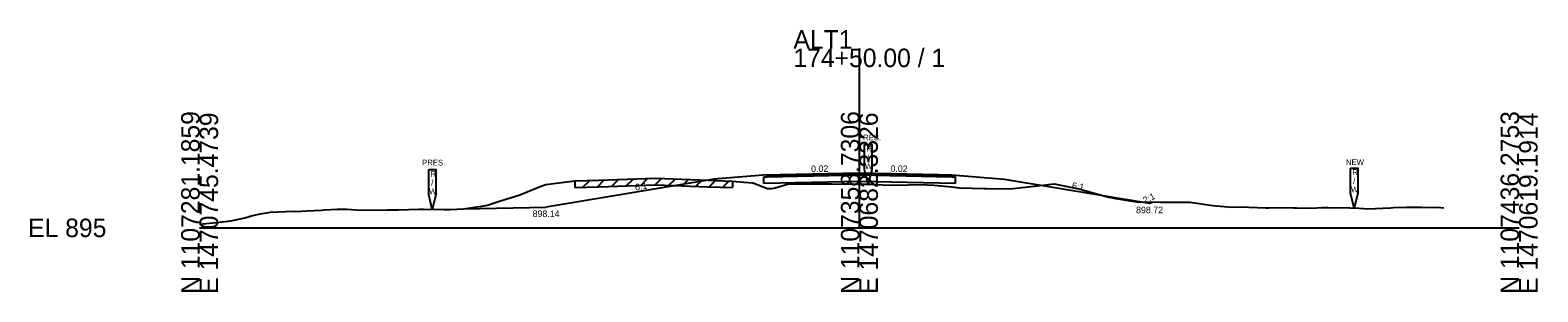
# Model space of a CAD drawing. Extents: x -26 to 2203, y -10 to 19568.
# Drawn here: x 974.3 to 1202.8, y 16490.3 to 16530 of the extents above; entities that cross this region are included whole.
import ezdxf

# ---------------------------------------------------------------- set-up
doc = ezdxf.new("R2010")
doc.units = 0
for name, color, linetype in [('RD_GPK_XS_Cell', 7, 'Continuous'), ('RD_XS_Base', 7, 'Continuous'), ('RD_XS_ExGround', 7, 'Continuous'), ('RD_XS_ExPaveRet', 7, 'Continuous'), ('RD_XS_ExRW', 7, 'Continuous'), ('RD_XS_Greenside', 7, 'Continuous'), ('RD_XS_NewRW', 7, 'Continuous'), ('RD_XS_Pave', 7, 'Continuous'), ('RD_XS_TieSlope', 7, 'Continuous'), ('RD_XS_TX_Ditch', 7, 'Continuous'), ('RD_XS_TX_Slope', 7, 'Continuous')]:
    doc.layers.add(name, color=color, linetype=linetype)

msp = doc.modelspace()

# ---------------------------------------------------------------- linework, layer by layer
at = {"layer": 'RD_GPK_XS_Cell'}
for p, q in [((1100, 16500), (1100, 16527.16)), ((1000, 16500), (1100, 16500)), ((1100, 16500), (1200, 16500))]:
    msp.add_line(p, q, dxfattribs=at)
at = {"layer": 'RD_XS_Base'}
for points in [[(1085.5, 16507.73), (1086, 16507.74), (1100, 16508.02), (1114, 16507.74), (1114.5, 16507.73)], [(1085.5, 16506.73), (1085.5, 16507.73)], [(1114.5, 16506.73), (1100, 16507.02), (1085.5, 16506.73)], [(1114.5, 16507.73), (1114.5, 16506.73)]]:
    msp.add_lwpolyline(points, dxfattribs=at)
at = {"layer": 'RD_XS_ExGround'}
msp.add_lwpolyline([(1000, 16500.56), (1002.98, 16500.88), (1004.71, 16501.05), (1006.85, 16501.54), (1008.02, 16501.87), (1009.46, 16502.16), (1010.16, 16502.29), (1010.72, 16502.36), (1014.21, 16502.51), (1014.59, 16502.5), (1016.25, 16502.59), (1018.46, 16502.68), (1018.96, 16502.75), (1020.82, 16502.83), (1022.33, 16502.83), (1023.71, 16502.75), (1026.2, 16502.7), (1028.47, 16502.74), (1030.07, 16502.75), (1033.22, 16502.81), (1033.93, 16502.83), (1037.08, 16502.77), (1037.97, 16502.77), (1040.01, 16502.89), (1042.78, 16503.3), (1043.63, 16503.43), (1045.45, 16504.04), (1048.54, 16505.03), (1051.61, 16506.26), (1052.46, 16506.56), (1054.85, 16506.89), (1056.87, 16507.12), (1060.44, 16507.24), (1069.16, 16507.51), (1077.08, 16507.21), (1080.78, 16507.1), (1082.51, 16506.92), (1083.83, 16506.8), (1086.05, 16505.94), (1086.79, 16505.94), (1087.21, 16506.06), (1089.28, 16506.67), (1091.72, 16506.69), (1093.32, 16506.67), (1094.98, 16506.67), (1095.83, 16506.67), (1100, 16506.64), (1101.85, 16506.61), (1103.57, 16506.51), (1104.49, 16506.48), (1107.44, 16506.53), (1109.24, 16506.58), (1111.31, 16506.46), (1113.99, 16506.2), (1115.18, 16506.09), (1118.92, 16505.96), (1119.3, 16505.95), (1122.88, 16505.9), (1126.94, 16506.37), (1129.51, 16506.66), (1133.5, 16505.87), (1134.52, 16505.57), (1137.74, 16504.64), (1138.1, 16504.58), (1138.88, 16504.45), (1141.99, 16503.96), (1142.75, 16503.94), (1145.63, 16503.87), (1146.69, 16503.88), (1147, 16503.89), (1150.11, 16503.9), (1153.58, 16503.38), (1156.42, 16503.14), (1157.78, 16503.21), (1161.6, 16503.06), (1162.05, 16503.06), (1165.47, 16503.08), (1165.82, 16503.05), (1166.25, 16503.03), (1167.95, 16502.97), (1169.34, 16503.05), (1170.09, 16503.09), (1171, 16503.07), (1172.22, 16503.06), (1173.21, 16503.09), (1174.35, 16503.06), (1175.75, 16502.96), (1177.08, 16502.88), (1180.51, 16503.05), (1180.95, 16503.07), (1182.88, 16503.12), (1184.81, 16503.13), (1185.26, 16503.13), (1187.15, 16503.11), (1187.69, 16503.16), (1188.59, 16503.04)], dxfattribs=at)
at = {"layer": 'RD_XS_ExPaveRet'}
for p, q in [((1056.87, 16507.06), (1056.93, 16507.13)), ((1056.87, 16507.12), (1056.87, 16506.12)), ((1058.09, 16506.16), (1059.12, 16507.2)), ((1060.28, 16506.23), (1061.32, 16507.27)), ((1062.47, 16506.3), (1063.51, 16507.33)), ((1064.66, 16506.37), (1065.69, 16507.4)), ((1066.85, 16506.44), (1067.88, 16507.47)), ((1069.04, 16506.51), (1070.01, 16507.48)), ((1071.09, 16506.44), (1072.06, 16507.4)), ((1073.14, 16506.36), (1074.1, 16507.32)), ((1075.18, 16506.28), (1076.15, 16507.25)), ((1077.23, 16506.21), (1078.2, 16507.18)), ((1079.29, 16506.15), (1080.26, 16507.12)), ((1080.78, 16507.1), (1080.78, 16506.1))]:
    msp.add_line(p, q, dxfattribs=at)
msp.add_lwpolyline([(1056.87, 16506.12), (1060.47, 16506.24), (1069.15, 16506.51), (1077.05, 16506.21), (1080.78, 16506.1)], dxfattribs=at)
at = {"layer": 'RD_XS_ExRW'}
for points in [[(1100.78, 16512.63), (1101.88, 16512.63), (1101.88, 16508.8), (1101.33, 16506.61), (1100.78, 16508.8)], [(1034.72, 16508.82), (1035.81, 16508.82), (1035.81, 16504.99), (1035.26, 16502.8), (1034.72, 16504.99)]]:
    msp.add_lwpolyline(points, close=True, dxfattribs=at)
at = {"layer": 'RD_XS_Greenside'}
msp.add_line((1040.01, 16502.89), (1052.52, 16503.14), dxfattribs=at)
for points in [[(1078, 16507.39), (1052.52, 16503.14)], [(1086, 16508.05), (1078, 16507.39)], [(1114, 16508.05), (1122, 16507.39)], [(1122, 16507.39), (1144, 16503.72)]]:
    msp.add_lwpolyline(points, dxfattribs=at)
at = {"layer": 'RD_XS_NewRW'}
msp.add_lwpolyline([(1174.45, 16509.03), (1175.55, 16509.03), (1175.55, 16505.2), (1175, 16503.01), (1174.45, 16505.2)], close=True, dxfattribs=at)
at = {"layer": 'RD_XS_Pave'}
for points in [[(1086, 16508.05), (1088, 16508.09), (1100, 16508.33), (1112, 16508.09), (1114, 16508.05)], [(1086, 16507.89), (1100, 16508.17), (1114, 16507.89)], [(1114, 16507.89), (1100, 16508.17), (1086, 16507.89)], [(1086, 16507.89), (1086, 16508.05)], [(1114, 16507.74), (1100, 16508.02), (1086, 16507.74)], [(1086, 16507.74), (1086, 16507.89)], [(1114, 16508.05), (1114, 16507.89)], [(1114, 16507.89), (1114, 16507.74)]]:
    msp.add_lwpolyline(points, dxfattribs=at)
at = {"layer": 'RD_XS_TieSlope'}
msp.add_lwpolyline([(1144, 16503.72), (1144.36, 16503.9)], dxfattribs=at)

# ---------------------------------------------------------------- texts
at = {"layer": 'RD_GPK_XS_Cell'}
for s, p in [('ALT1', (1090, 16527.16)), ('174+50.00 / 1', (1090, 16524.36)), ('EL 895', (974, 16498.6))]:
    msp.add_text(s, height=2.8, dxfattribs=at).set_placement(p)
for s, p in [('N 1107281.1859', (1000, 16490)), ('E 1470745.4739', (1002.8, 16490)), ('N 1107358.7306', (1100, 16490)), ('E 1470682.3326', (1102.8, 16490)), ('N 1107436.2753', (1200, 16490)), ('E 1470619.1914', (1202.8, 16490))]:
    msp.add_text(s, height=2.8, rotation=90, dxfattribs=at).set_placement(p)
at = {"layer": 'RD_XS_ExRW'}
for s, p in [('PRES.', (1099.78, 16513.26)), ('R', (1101.04, 16511.54)), ('PRES.', (1033.72, 16509.45)), ('W', (1100.86, 16508.91)), ('/', (1101.16, 16510.23)), ('R', (1034.98, 16507.73)), ('/', (1035.1, 16506.42)), ('W', (1034.79, 16505.1))]:
    msp.add_text(s, height=0.875, dxfattribs=at).set_placement(p)
at = {"layer": 'RD_XS_NewRW'}
for s, p in [('NEW', (1173.75, 16509.51)), ('R', (1174.71, 16507.99)), ('/', (1174.83, 16506.68)), ('W', (1174.53, 16505.37))]:
    msp.add_text(s, height=0.875, dxfattribs=at).set_placement(p)
at = {"layer": 'RD_XS_TX_Ditch'}
msp.add_text('898.14', height=1, dxfattribs=at).set_placement((1050.47, 16501.64))
at = {"layer": 'RD_XS_TX_Slope'}
for s, rotation, p in [('0.02', 1.1458, (1092.69, 16508.44)), ('0.02', 358.8542, (1104.7, 16508.49)), ('6:1', 9.4642, (1066.07, 16505.65)), ('6:1', 350.5358, (1132.16, 16505.95)), ('2:1', 26.5651, (1143.27, 16503.63))]:
    msp.add_text(s, height=1, rotation=rotation, dxfattribs=at).set_placement(p)
msp.add_text('898.72', height=1, dxfattribs=at).set_placement((1141.94, 16502.22))

doc.saveas('drawing.dxf')
